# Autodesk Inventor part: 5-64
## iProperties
Company: HERDT-Verlag
Shininess: 64.0
Length Units: 11269
Angle Units: 11279
Time Units: 11290
Mass Units: 11283
Length Display Precision: 3
Angle Display Precision: 2
Compacted: True
Part Number: 5-64
Document SubType Name: Modeling
Created: 2006-01
Material: Standard
Designer: Eichenseer
Checked By: G. Lehmann
Engr Approved By: M. Grouls
Project: Inventor 11 - Grundkurs
Density: 0.0
Volumn: 0.0
Area: 0.0
PropertySet Name: Model Information
Control State: 0
Master: False
Checked Out: False
Author: P. Tropf
Subject: Inventor 10 - Grundkurs
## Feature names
1. Extrusion1
2. Rundung1 [Fillet]
